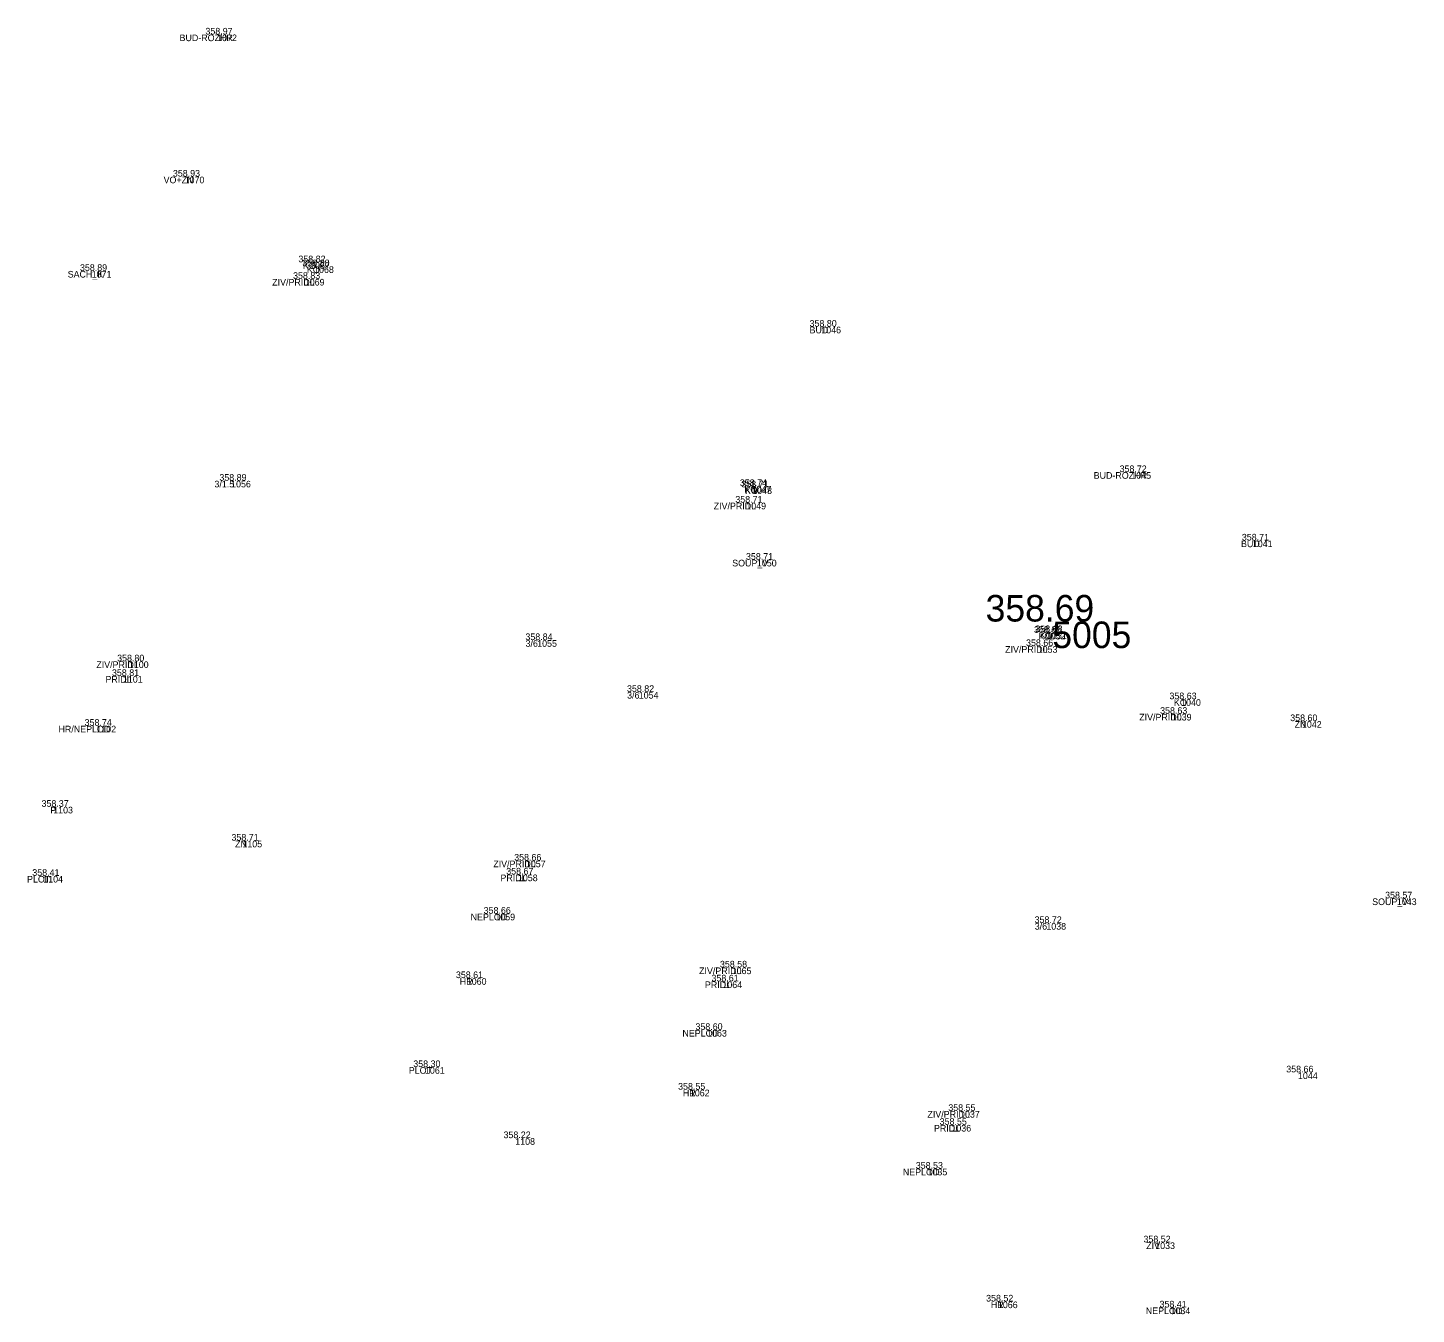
# Model space of a CAD drawing. Extents: x -590413 to -590216, y -1129419 to -1129249.
# Drawn here: x -590315.25 to -590294.34, y -1129304.51 to -1129285.14 of the extents above; entities that cross this region are included whole.
import ezdxf

# ---------------------------------------------------------------- set-up
doc = ezdxf.new("R2010")
doc.units = 0
for name, color, linetype in [('Vrstva B24', 7, 'Continuous'), ('Vrstva B54', 7, 'Continuous'), ('Vrstva B55', 7, 'Continuous'), ('Vrstva B56', 7, 'Continuous'), ('Vrstva B58', 7, 'Continuous'), ('Vrstva B59', 7, 'Continuous'), ('Vrstva B60', 7, 'Continuous')]:
    doc.layers.add(name, color=color, linetype=linetype)

msp = doc.modelspace()

# ---------------------------------------------------------------- linework, layer by layer
at = {"layer": 'Vrstva B56'}
msp.add_line((-590299.82, -1129294.08), (-590299.82, -1129294.08), dxfattribs=at)
at = {"layer": 'Vrstva B60'}
for p, q in [((-590312.4, -1129285.24), (-590312.4, -1129285.24)), ((-590312.89, -1129287.38), (-590312.89, -1129287.38)), ((-590314.29, -1129288.8), (-590314.29, -1129288.8)), ((-590311, -1129288.67), (-590311, -1129288.67)), ((-590310.94, -1129288.73), (-590310.94, -1129288.73)), ((-590311.08, -1129288.92), (-590311.08, -1129288.92)), ((-590303.3, -1129289.64), (-590303.3, -1129289.64)), ((-590298.63, -1129291.83), (-590298.63, -1129291.83)), ((-590312.19, -1129291.96), (-590312.19, -1129291.96)), ((-590304.35, -1129292.04), (-590304.35, -1129292.04)), ((-590304.34, -1129292.06), (-590304.34, -1129292.06)), ((-590304.43, -1129292.29), (-590304.43, -1129292.29)), ((-590296.8, -1129292.86), (-590296.8, -1129292.86)), ((-590304.27, -1129293.15), (-590304.27, -1129293.15)), ((-590299.92, -1129294.25), (-590299.92, -1129294.25)), ((-590299.9, -1129294.24), (-590299.9, -1129294.24)), ((-590307.58, -1129294.36), (-590307.58, -1129294.36)), ((-590300.04, -1129294.45), (-590300.04, -1129294.45)), ((-590313.73, -1129294.68), (-590313.73, -1129294.68)), ((-590313.82, -1129294.9), (-590313.82, -1129294.9)), ((-590306.05, -1129295.14), (-590306.05, -1129295.14)), ((-590297.88, -1129295.25), (-590297.88, -1129295.25)), ((-590298.02, -1129295.47), (-590298.02, -1129295.47)), ((-590314.22, -1129295.65), (-590314.22, -1129295.65)), ((-590296.06, -1129295.58), (-590296.06, -1129295.58)), ((-590314.87, -1129296.87), (-590314.87, -1129296.87)), ((-590312.02, -1129297.38), (-590312.02, -1129297.38)), ((-590307.75, -1129297.68), (-590307.75, -1129297.68)), ((-590315.02, -1129297.91), (-590315.02, -1129297.91)), ((-590307.87, -1129297.89), (-590307.87, -1129297.89)), ((-590294.63, -1129298.25), (-590294.63, -1129298.25)), ((-590308.21, -1129298.48), (-590308.21, -1129298.48)), ((-590299.91, -1129298.62), (-590299.91, -1129298.62)), ((-590308.64, -1129299.45), (-590308.64, -1129299.45)), ((-590304.65, -1129299.29), (-590304.65, -1129299.29)), ((-590304.79, -1129299.5), (-590304.79, -1129299.5)), ((-590305.02, -1129300.23), (-590305.02, -1129300.23)), ((-590309.27, -1129300.79), (-590309.27, -1129300.79)), ((-590296.12, -1129300.87), (-590296.12, -1129300.87)), ((-590305.28, -1129301.13), (-590305.28, -1129301.13)), ((-590301.21, -1129301.45), (-590301.21, -1129301.45)), ((-590301.34, -1129301.66), (-590301.34, -1129301.66)), ((-590307.91, -1129301.86), (-590307.91, -1129301.86)), ((-590301.7, -1129302.32), (-590301.7, -1129302.32)), ((-590298.27, -1129303.43), (-590298.27, -1129303.43)), ((-590300.64, -1129304.32), (-590300.64, -1129304.32)), ((-590298.04, -1129304.41), (-590298.04, -1129304.41))]:
    msp.add_line(p, q, dxfattribs=at)

# ---------------------------------------------------------------- texts
at = {"layer": 'Vrstva B24'}
for s, p in [('BUD-ROZHR', (-590312.967, -1129285.34)), ('VO+ZN', (-590313.207, -1129287.48)), ('SACH_K', (-590314.652, -1129288.9)), ('KO', (-590311.109, -1129288.77)), ('KO', (-590311.049, -1129288.83)), ('ZIV/PRIDL', (-590311.571, -1129289.02)), ('BUD', (-590303.477, -1129289.74)), ('BUD-ROZHR', (-590299.197, -1129291.93)), ('3/1.5', (-590312.441, -1129292.06)), ('KO', (-590304.459, -1129292.14)), ('KO', (-590304.449, -1129292.16)), ('ZIV/PRIDL', (-590304.921, -1129292.39)), ('BUD', (-590296.977, -1129292.96)), ('SOUP_V', (-590304.642, -1129293.25)), ('KO', (-590300.029, -1129294.35)), ('KO', (-590300.009, -1129294.34)), ('3/6', (-590307.755, -1129294.46)), ('ZIV/PRIDL', (-590300.531, -1129294.55)), ('ZIV/PRIDL', (-590314.221, -1129294.78)), ('PRIDL', (-590314.083, -1129295)), ('3/6', (-590306.225, -1129295.24)), ('KO', (-590297.989, -1129295.35)), ('ZIV/PRIDL', (-590298.511, -1129295.57)), ('HR/NEPLOD', (-590314.79, -1129295.75)), ('ZN', (-590296.17, -1129295.68)), ('P', (-590314.914, -1129296.97)), ('ZN', (-590312.13, -1129297.48)), ('ZIV/PRIDL', (-590308.241, -1129297.78)), ('PLOT', (-590315.264, -1129298.01)), ('PRIDL', (-590308.133, -1129297.99)), ('SOUP_V', (-590295.002, -1129298.35)), ('NEPLOD', (-590308.582, -1129298.58)), ('3/6', (-590300.085, -1129298.72)), ('HR', (-590308.746, -1129299.55)), ('ZIV/PRIDL', (-590305.141, -1129299.39)), ('PRIDL', (-590305.053, -1129299.6)), ('NEPLOD', (-590305.392, -1129300.33)), ('PLOT', (-590309.514, -1129300.89)), ('HR', (-590305.386, -1129301.23)), ('ZIV/PRIDL', (-590301.701, -1129301.55)), ('PRIDL', (-590301.603, -1129301.76)), ('NEPLOD', (-590302.072, -1129302.42)), ('ZIV', (-590298.406, -1129303.53)), ('HR', (-590300.746, -1129304.42)), ('NEPLOD', (-590298.412, -1129304.51))]:
    msp.add_text(s, height=0.1, dxfattribs=at).set_placement(p)
at = {"layer": 'Vrstva B54'}
msp.add_text('358.69', height=0.4, dxfattribs=at).set_placement((-590300.825, -1129294.08))
at = {"layer": 'Vrstva B55'}
msp.add_text('5005', height=0.4, dxfattribs=at).set_placement((-590299.82, -1129294.48))
at = {"layer": 'Vrstva B58'}
for s, p in [('358.97', (-590312.577, -1129285.24)), ('358.93', (-590313.067, -1129287.38)), ('358.82', (-590311.177, -1129288.67)), ('358.89', (-590314.467, -1129288.8)), ('358.88', (-590311.117, -1129288.73)), ('358.83', (-590311.257, -1129288.92)), ('358.80', (-590303.477, -1129289.64)), ('358.72', (-590298.807, -1129291.83)), ('358.89', (-590312.367, -1129291.96)), ('358.74', (-590304.527, -1129292.04)), ('358.71', (-590304.505, -1129292.06)), ('358.71', (-590304.595, -1129292.29)), ('358.71', (-590296.965, -1129292.86)), ('358.71', (-590304.435, -1129293.15)), ('358.66', (-590300.096, -1129294.25)), ('358.68', (-590300.076, -1129294.24)), ('358.84', (-590307.757, -1129294.36)), ('358.66', (-590300.216, -1129294.45)), ('358.80', (-590313.907, -1129294.68)), ('358.81', (-590313.985, -1129294.9)), ('358.82', (-590306.227, -1129295.14)), ('358.63', (-590298.056, -1129295.25)), ('358.63', (-590298.196, -1129295.47)), ('358.60', (-590296.236, -1129295.58)), ('358.74', (-590314.397, -1129295.65)), ('358.37', (-590315.046, -1129296.87)), ('358.71', (-590312.185, -1129297.38)), ('358.66', (-590307.926, -1129297.68)), ('358.67', (-590308.046, -1129297.89)), ('358.41', (-590315.185, -1129297.91)), ('358.57', (-590294.807, -1129298.25)), ('358.66', (-590308.386, -1129298.48)), ('358.72', (-590300.087, -1129298.62)), ('358.58', (-590304.827, -1129299.29)), ('358.61', (-590308.804, -1129299.45)), ('358.61', (-590304.954, -1129299.5)), ('358.60', (-590305.196, -1129300.23)), ('358.30', (-590309.446, -1129300.79)), ('358.66', (-590296.296, -1129300.87)), ('358.55', (-590305.457, -1129301.13)), ('358.55', (-590301.387, -1129301.45)), ('358.55', (-590301.517, -1129301.66)), ('358.22', (-590308.087, -1129301.86)), ('358.53', (-590301.877, -1129302.32)), ('358.52', (-590298.447, -1129303.43)), ('358.52', (-590300.817, -1129304.32)), ('358.41', (-590298.205, -1129304.41))]:
    msp.add_text(s, height=0.1, dxfattribs=at).set_placement(p)
at = {"layer": 'Vrstva B59'}
for s, p in [('1072', (-590312.4, -1129285.34)), ('1070', (-590312.89, -1129287.48)), ('1071', (-590314.29, -1129288.9)), ('1067', (-590311, -1129288.77)), ('1068', (-590310.94, -1129288.83)), ('1069', (-590311.08, -1129289.02)), ('1046', (-590303.3, -1129289.74)), ('1045', (-590298.63, -1129291.93)), ('1056', (-590312.19, -1129292.06)), ('1047', (-590304.35, -1129292.14)), ('1048', (-590304.34, -1129292.16)), ('1049', (-590304.43, -1129292.39)), ('1041', (-590296.8, -1129292.96)), ('1050', (-590304.27, -1129293.25)), ('1052', (-590299.92, -1129294.35)), ('1051', (-590299.9, -1129294.34)), ('1055', (-590307.58, -1129294.46)), ('1053', (-590300.04, -1129294.55)), ('1100', (-590313.73, -1129294.78)), ('1101', (-590313.82, -1129295)), ('1054', (-590306.05, -1129295.24)), ('1040', (-590297.88, -1129295.35)), ('1039', (-590298.02, -1129295.57)), ('1102', (-590314.22, -1129295.75)), ('1042', (-590296.06, -1129295.68)), ('1103', (-590314.87, -1129296.97)), ('1105', (-590312.02, -1129297.48)), ('1057', (-590307.75, -1129297.78)), ('1104', (-590315.02, -1129298.01)), ('1058', (-590307.87, -1129297.99)), ('1043', (-590294.63, -1129298.35)), ('1059', (-590308.21, -1129298.58)), ('1038', (-590299.91, -1129298.72)), ('1060', (-590308.64, -1129299.55)), ('1065', (-590304.65, -1129299.39)), ('1064', (-590304.79, -1129299.6)), ('1063', (-590305.02, -1129300.33)), ('1061', (-590309.27, -1129300.89)), ('1044', (-590296.12, -1129300.97)), ('1062', (-590305.28, -1129301.23)), ('1037', (-590301.21, -1129301.55)), ('1036', (-590301.34, -1129301.76)), ('1108', (-590307.91, -1129301.96)), ('1035', (-590301.7, -1129302.42)), ('1033', (-590298.27, -1129303.53)), ('1066', (-590300.64, -1129304.42)), ('1034', (-590298.04, -1129304.51))]:
    msp.add_text(s, height=0.1, dxfattribs=at).set_placement(p)

doc.saveas('drawing.dxf')
